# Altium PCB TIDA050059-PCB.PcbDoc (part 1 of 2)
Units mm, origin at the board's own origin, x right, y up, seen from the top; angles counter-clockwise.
Board outline 100 x 120.38 mm, 2 copper layers (Top Layer, Bottom Layer), stack 1.575 mm thick; 126 components, 42 nets, 240 pads, 89 vias.
Unrouted connection lines stored in the file: 41.
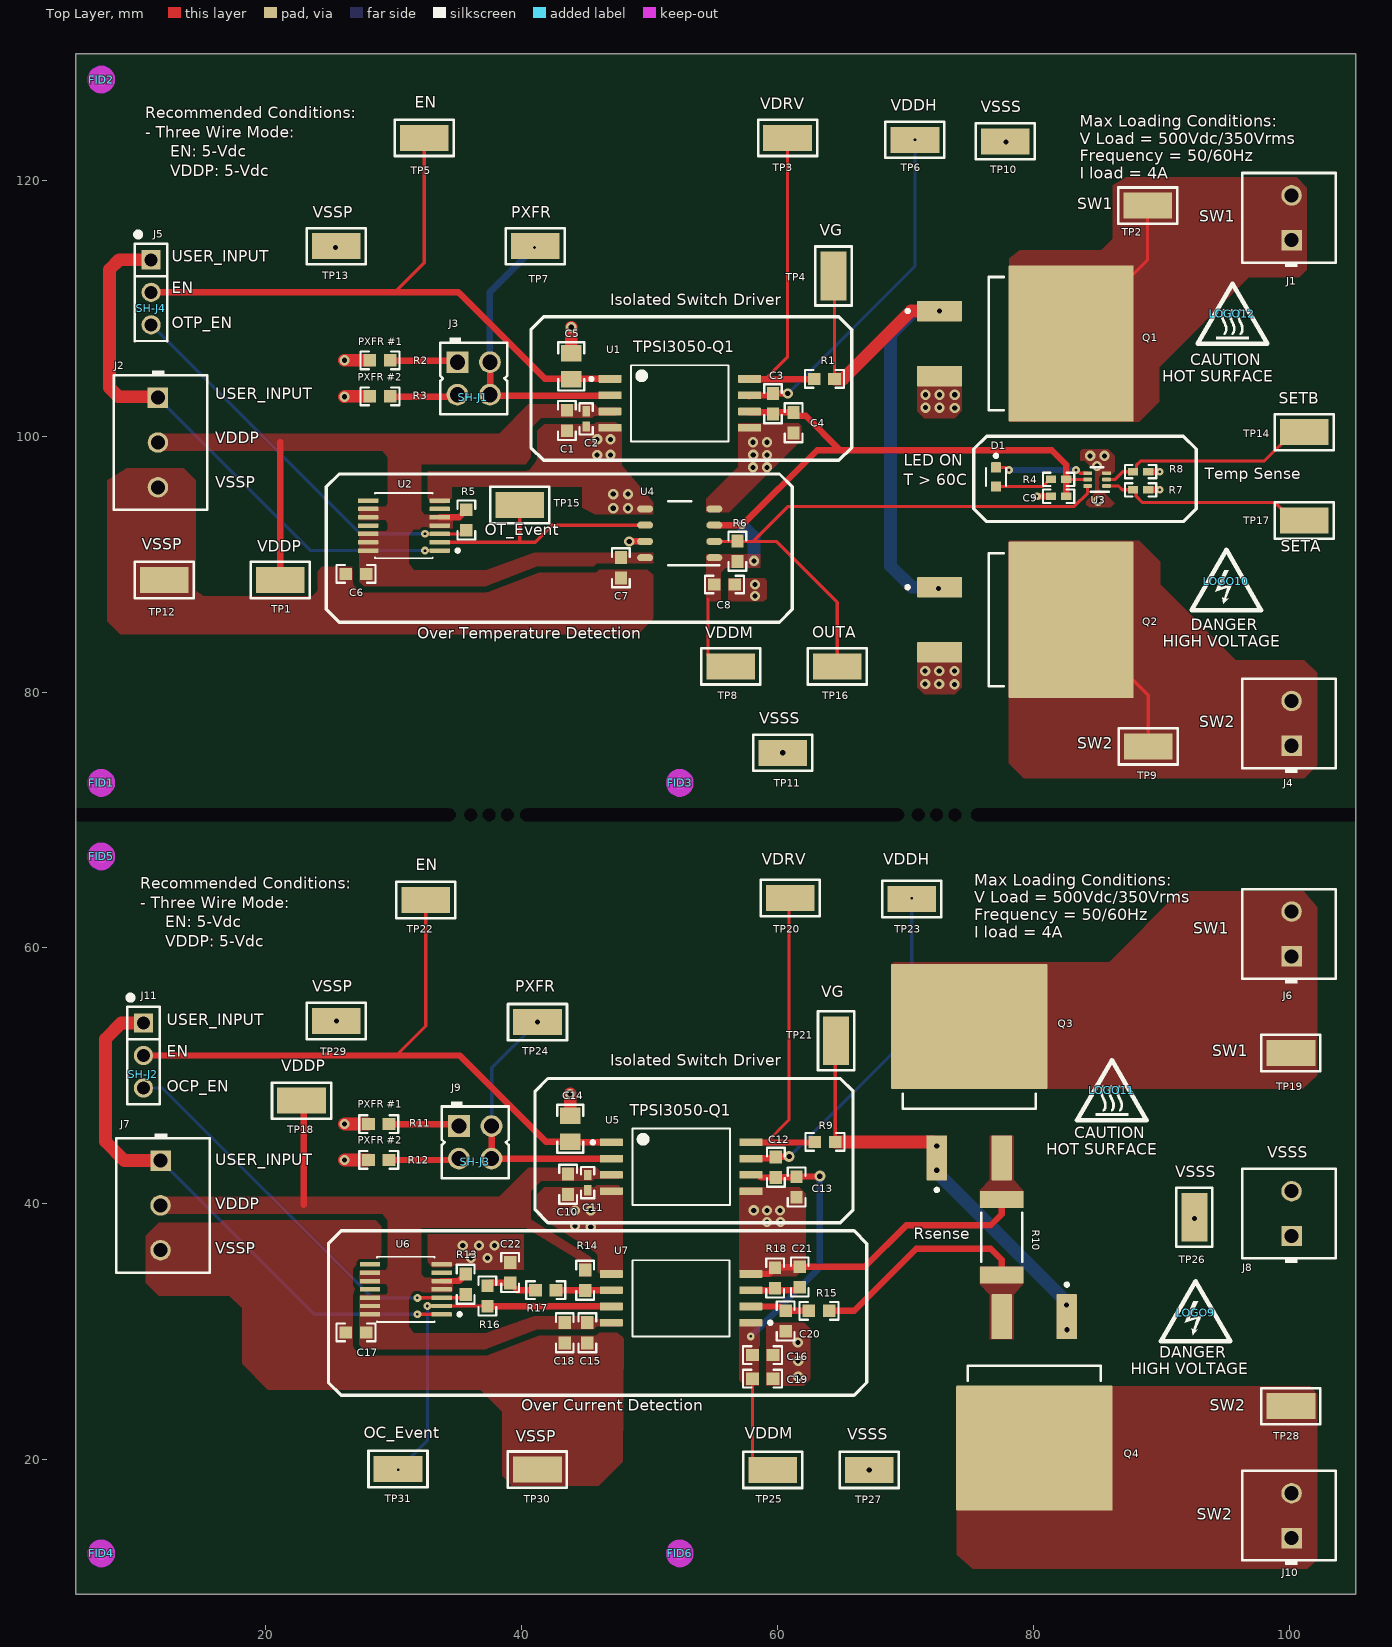
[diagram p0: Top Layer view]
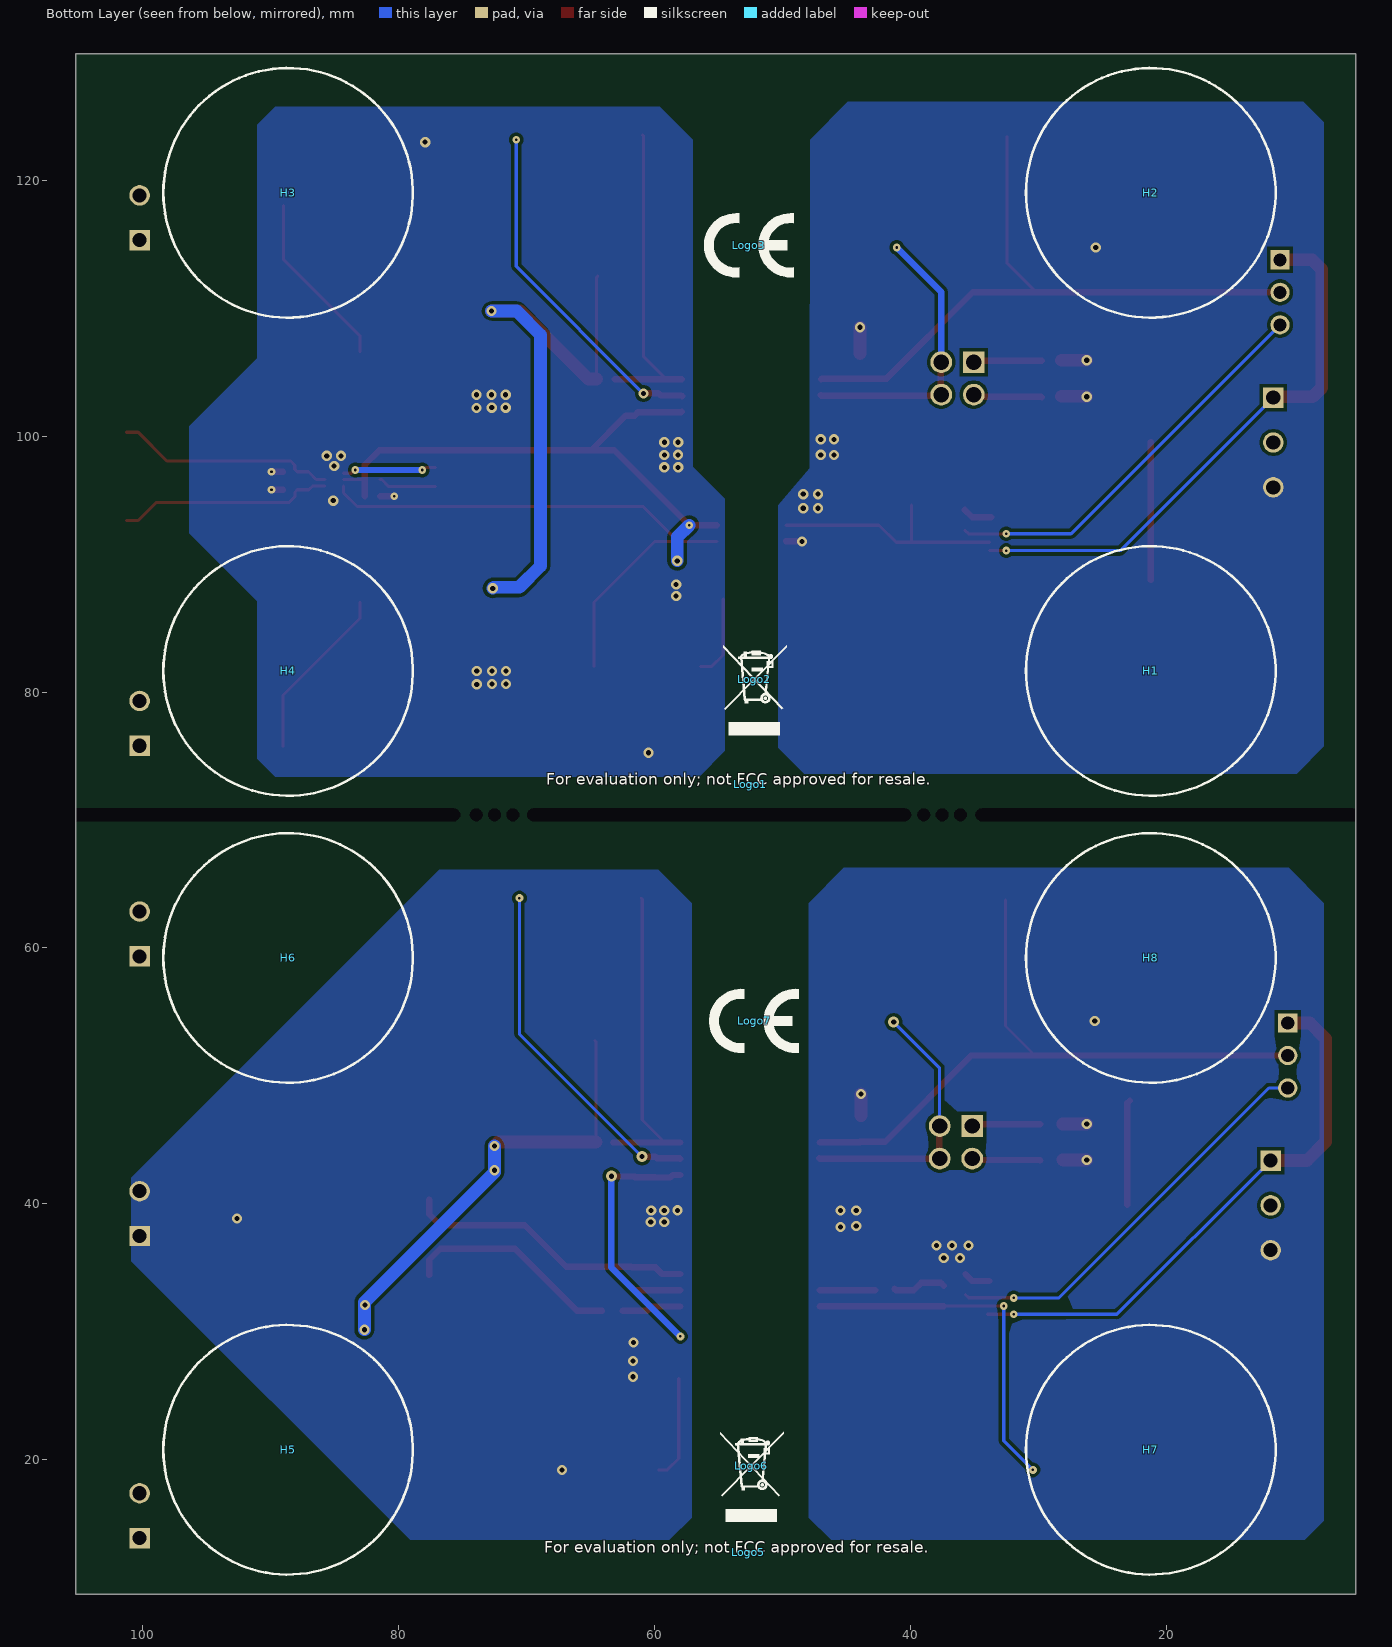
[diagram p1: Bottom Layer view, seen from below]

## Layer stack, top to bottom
Top Solder: solder mask 0.0102, Solder Resist, Dk 3.5
Top Layer: signal copper 0.0356
Dielectric1: core 1.5037, FR-4 High Tg, Dk 4.8
Bottom Layer: signal copper 0.0356
Bottom Solder: solder mask 0.0102, Solder Resist, Dk 3.5

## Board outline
5.2,9.5 105.2,9.5 105.2,129.875 5.2,129.875

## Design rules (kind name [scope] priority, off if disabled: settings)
AcuteAngle [All] p1: minimum=4.50000000000000E+0001 checktracksonly=FALSE
AssemblyTestPointUsage [All] p1: valid=2
BoardOutlineClearance BoardOutlineClearance_MountingHoles [OnCopper and InComponentClass('Mounting Holes')] p1: gap=1 ignorepadtopadclearanceinfootprint=FALSE
BoardOutlineClearance BoardOutlineClearance_Poly [OnCopper and IsPoly] p2: gap=0.635 ignorepadtopadclearanceinfootprint=FALSE
BoardOutlineClearance [OnCopper and Not InComponentClass('Logo') and not InComponentClass('FiducialMark') and not InRegion(1000,500,4000,800) and not InPoly] p3: gap=1.016 ignorepadtopadclearanceinfootprint=FALSE
Clearance Clearance_Keepouts [((IsTrack Or IsArc) And Not InPoly) And IsFree and IsKeepOut vs ((IsTrack Or IsArc) And Not InPoly) And IsFree and IsKeepOut] p1: gap=0 ignorepadtopadclearanceinfootprint=FALSE
Clearance Clearance_Poly [InPolygon] p2: gap=0.254 ignorepadtopadclearanceinfootprint=TRUE except(0.5: Fill-Fill Fill-Poly Fill-Region Poly-Poly Poly-Region Region-Region)
Clearance Clearance_FiducialMark [IsKeepOut and InComponentClass('FiducialMark') vs IsPad and InComponentClass('FiducialMark')] p3: gap=0 ignorepadtopadclearanceinfootprint=FALSE
Clearance [All] p4: gap=0.2 ignorepadtopadclearanceinfootprint=TRUE
ComponentClearance ComponentClearance_MountingHoles_FiducialMarks [InComponentClass('Mounting Holes') vs InComponentClass('FiducialMark')] p1: gap=1.27 collisioncheckmode=3 verticalgap=0.254 showdistances=FALSE
ComponentClearance ComponentClearance_Shunt [InComponentClass('Header') vs InComponentClass('Shunt')] p2: gap=0 collisioncheckmode=3 verticalgap=0 showdistances=FALSE
ComponentClearance ComponentClearance_Logo [InComponentClass('Logo')] p3: gap=0.762 collisioncheckmode=3 verticalgap=0.254 showdistances=FALSE
ComponentClearance ComponentClearance_ScrewToNut [(HasFootprint('NY PMS 440 0025 PH')) vs (HasFootprint('Keystone_1902C'))] p4: gap=0.127 collisioncheckmode=3 verticalgap=0.254 showdistances=FALSE
ComponentClearance ComponentClearance_MountingHoles [InComponentClass('Mounting Holes')] p5: gap=2.54 collisioncheckmode=3 verticalgap=2540 showdistances=FALSE
ComponentClearance ComponentClearance_SmallPassives [HasFootprint('0201*') or HasFootprint('0402*') or HasFootprint('0508') or HasFootprint('0603*') or HasFootprint('0612') or HasFootprint('0805*') or HasFootprint('0815*') or HasFootprint('0830*') or HasFootprint('1206*') or HasFootprint('1210*') or HasFootprint('1808*') or HasFootprint('1812*') or HasFootprint('1825*') or HasFootprint('2010*') or HasFootprint('2220*') or HasFootprint('2225*') or HasFootprint('2512*') or HasFootprint('2728*') or HasFootprint('3518*') vs HasFootprint('0201*') or HasFootprint('0402*') or HasFootprint('0508') or HasFootprint('0603*') or HasFootprint('0612') or HasFootprint('0805*') or HasFootprint('0815*') or HasFootprint('0830*') or HasFootprint('1206*') or HasFootprint('1210*') or HasFootprint('1808*') or HasFootprint('1812*') or HasFootprint('1825*') or HasFootprint('2010*') or HasFootprint('2220*') or HasFootprint('2225*') or HasFootprint('2512*') or HasFootprint('2728*') or HasFootprint('3518*')] p6: gap=0.38 collisioncheckmode=3 verticalgap=0.254 showdistances=FALSE
ComponentClearance ComponentClearance_THtoSMT [IsThruComponent vs IsSMTComponent] p7: gap=0.762 collisioncheckmode=3 verticalgap=0.762 showdistances=FALSE
ComponentClearance ComponentClearance_THtoTH [IsThruComponent vs IsThruComponent] p8: gap=0.508 collisioncheckmode=3 verticalgap=0.762 showdistances=FALSE
ComponentClearance [All] p9: gap=0.508 collisioncheckmode=3 verticalgap=0.254 showdistances=FALSE
DiffPairsRouting [All] p1: maxlimit=2.54 minlimit=0.254 mostfreqgap=0.254 toplayer_minwidth=0.381 toplayer_maxwidth=0.381 toplayer_prefwidth=0.381 bottomlayer_minwidth=0.381 bottomlayer_maxwidth=0.381 bottomlayer_prefwidth=0.381 maxuncoupledlength=25.4
FabricationTestPointUsage TestPointUsage [All] p1: valid=2 allowmultiple=FALSE
FabricationTestpoint Testpoint [All] p1: side=3 testpointundercomponent=TRUE minsize=1.016 maxsize=2.54 preferedsize=1.524 minholesize=0 maxholesize=1.016 preferedholesize=0.813 testpointgrid=0.025 allowsidetop=TRUE allowsidebottom=TRUE usegrid=TRUE gridtolerance=0
FanoutControl Fanout_LCC [IsLCC] p1: bgadir=Out bgaviamode=Centered fanoutstyle=Auto fanoutdirection=Alternating viagrid=0.025 // Fanout_LCC (Default Rule)
FanoutControl Fanout_BGA [IsBGA] p2: bgadir=Out bgaviamode=Centered fanoutstyle=Auto fanoutdirection=Alternating viagrid=0.025 // Fanout_BGA (Default Rule)
FanoutControl Fanout_Default [All] p4: bgadir=Out bgaviamode=Centered fanoutstyle=Auto fanoutdirection=Alternating viagrid=0.025 // Fanout_Default (Default Rule)
FanoutControl Fanout_Small [(CompPinCount < 5)] p5: bgadir=Out bgaviamode=Centered fanoutstyle=Auto fanoutdirection=OutThenIn viagrid=0.025 // Fanout_Small (Default Rule)
HoleSize [All] p1: absolutevalues=TRUE maxlimit=6.375 minlimit=0.2 maxpercent=80.000 minpercent=20.000
MinimumAnnularRing MinimumAnnularRing_ThermalPadVias [IsVia and InAnyComponent] p1: minimumring=0.15
MinimumAnnularRing [All] p2: minimumring=0.2
MinimumSolderMaskSliver MinimumSolderMaskSliver_Logo [InComponentClass('Logo') vs InComponentClass('Logo')] p1: minsoldermaskwidth=0.018
MinimumSolderMaskSliver [All] p2: minsoldermaskwidth=0.1
PlaneClearance [All] p1: clearance=0.5
PlaneConnect [All] p1: planeconnectstyle=Direct reliefexpansion=0.254 reliefentries=4 reliefconductorwidth=0.254 reliefairgap=0.254
PolygonConnect [All] p1: connectstyle=Direct reliefconductorwidth=0.254 reliefentries=4 polygonreliefangle="90 Angle" airgapwidth=0.254
RoutingVias ThermalPadVias [IsVia and InAnyComponent] p1: holewidth=0.4 width=0.8 viastyle="Through Hole" minholewidth=0.2 minwidth=0.5 maxholewidth=1 maxwidth=1.6
RoutingVias [All] p2: holewidth=0.406 width=0.864 viastyle="Through Hole" minholewidth=0.2 minwidth=0.61 maxholewidth=1.016 maxwidth=1.651
SilkToBoardRegionClearance [Not ((IsComment or IsDesignator) And (Hide <> 'False')) and not InRegion(1000,500,4000,800)] p1:
SilkToSilkClearance SilkToSilkClearance_Pb-FreeLogo [(HasFootprint('Pb-Free_Overlay_Medium') OR HasFootprint('Pb-Free_Overlay_Small')) vs (HasFootprint('Pb-Free_Overlay_Medium') OR HasFootprint('Pb-Free_Overlay_Small'))] p1: silktosilkclearance=0
SilkToSilkClearance [All] p2: silktosilkclearance=0.1
SilkToSolderMaskClearance SilkToComponentPadClearance [(IsPad or IsFill or IsRegion) and InAnycomponent] p1: minsilkscreentomaskgap=0.127 clearancetoexposedcopper=TRUE
SilkToSolderMaskClearance "Silk to Solder Mask Opening" [All] p2: minsilkscreentomaskgap=0.1 clearancetoexposedcopper=FALSE
SolderMaskExpansion [All] p1: expansion=0.05 istentingtop=FALSE
UnRoutedNet [All] p1: checkbadconnections=TRUE
Width [All] p1: maxlimit=1 minlimit=0.25 preferedwidth=0.5 minimp=50.000000 maximp=50.000000 favimp=50.000000 checkconnectedcopper=TRUE
13 further rules are at their usual default settings.

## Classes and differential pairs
component class TIDA050059-Schematic_2: C10 C11 C12 C13 C14 C15 C16 C17 C18 C19 C20 C21 C22 J6 J7 J8 J9 J10 J11 Q3 Q4 R9 R10 R11 R12 R13 R14 R15 R16 R17 R18 SH-J3 SH-J4 TP18 TP19 TP20 TP21 TP22 TP23 TP24 TP25 TP26 TP27 TP28 TP29 TP30 TP31 U5 U6 U7
component class TIDA050059-Schematic_1: C1 C2 C3 C4 C5 C6 C7 C8 C9 D1 J1 J2 J3 J4 J5 Q1 Q2 R1 R2 R3 R4 R5 R6 R7 R8 SH-J1 SH-J2 TP1 TP2 TP3 TP4 TP5 TP6 TP7 TP8 TP9 TP10 TP11 TP12 TP13 TP14 TP15 TP16 TP17 U1 U2 U3 U4
component class Shunt: SH-J1 SH-J2 SH-J3 SH-J4
component class Header: J3 J5 J9 J11
component class TIDA050059-Hardware: FID1 FID2 FID3 FID4 FID5 FID6 H1 H2 H3 H4 H5 H6 H7 H8 Logo1 Logo2 Logo3 Logo5 Logo6 Logo7 LOGO9 LOGO10 LOGO11 LOGO12 ZZ1 ZZ2 ZZ3 ZZ4
component class FiducialMark: FID1 FID2 FID3 FID4 FID5 FID6
component class AssemblyNote: ZZ1 ZZ2 ZZ3 ZZ4

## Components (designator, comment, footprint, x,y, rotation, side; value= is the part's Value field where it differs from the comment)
C1 "GRM188R71E224KA88D" 0603 43.586,101.213 r270 top value=0.22uF
C2 "GRM155R71E104KE14D" 0402 45.089,101.338 r270 top value=0.1uF
C3 "UMK107AB7105KA-T" 0603 59.681,102.513 r270 top value=1uF
C4 "UMK107AB7105KA-T" 0603 61.298,101.038 r270 top value=1uF
C5 "C0805C104K1RACTU" 0805_HV 43.922,105.44 r90 top value=0.1uF
C6 "GCM188R71E104KA57D" 0603 27.11,89.225 r180 top value=0.1uF
C7 "GCM188R71E104KA57D" 0603 47.797,89.7 r270 top value=0.1uF
C8 "GCM188R71E104KA57D" 0603 55.9,88.4 r180 top value=0.1uF
C9 "GRM155R71E104KE14D" 0402 82,95.295 r0 top value=0.1uF
C10 "GRM188R71E224KA88D" 0603 43.675,41.55 r270 top value=0.22uF
C11 "GRM155R71E104KE14D" 0402 45.2,41.675 r270 top value=0.1uF
C12 "UMK107AB7105KA-T" 0603 59.9,42.87 r270 top value=1uF
C13 "UMK107AB7105KA-T" 0603 61.525,41.33 r270 top value=1uF
C14 "C0805C104K1RACTU" 0805_HV 43.85,45.875 r90 top value=0.1uF
C15 "GCM188R71E104KA57D" 0603 45.177,29.95 r270 top value=0.1uF
C16 "GCM188R71E104KA57D" 0603 58.873,28.2 r180 top value=0.1uF
C17 "GCM188R71E104KA57D" 0603 27.1,29.971 r180 top value=0.1uF
C18 "GCM188R71E105KA64D" 0603 43.413,29.935 r270 top value=1uF
C19 "GCM188R71E105KA64D" 0603 58.873,26.35 r180 top value=1uF
C20 "C1608X7R1H103K080AA" 0603 60.675,30.855 r270 top value=0.01uF
C21 "C0603C102J5RACTU" 0603 61.775,34.3 r90 top value=1000pF
C22 "CGA3E3X7R1H224K080AB" 0603 39.157,34.639 r90 top value=0.22uF
D1 "LSL29K-G1H2-1-Z" FP-LSL29K-G1H2-1-Z_0603-0 77.1,96.8 r270 top
FID1 "Fiducial" Fiducial10-20 7.2,72.9 r0 top
FID2 "Fiducial" Fiducial10-20 7.2,127.85 r0 top
FID3 "Fiducial" Fiducial10-20 52.4,72.9 r0 top
FID4 "Fiducial" Fiducial10-20 7.2,12.7 r0 top
FID5 "Fiducial" Fiducial10-20 7.2,67.158 r0 top
FID6 "Fiducial" Fiducial10-20 52.4,12.7 r0 top
H1 "SJ-5017 (BLACK)" 3M_SJ-5017BLACK 21.2,81.644 r180 bottom
H2 "SJ-5017 (BLACK)" 3M_SJ-5017BLACK 21.2,119 r180 bottom
H3 "SJ-5017 (BLACK)" 3M_SJ-5017BLACK 88.6,119 r180 bottom
H4 "SJ-5017 (BLACK)" 3M_SJ-5017BLACK 88.6,81.644 r180 bottom
H5 "SJ-5017 (BLACK)" 3M_SJ-5017BLACK 88.6,20.8 r180 bottom
H6 "SJ-5017 (BLACK)" 3M_SJ-5017BLACK 88.6,59.225 r180 bottom
H7 "SJ-5017 (BLACK)" 3M_SJ-5017BLACK 21.2,20.8 r180 bottom
H8 "SJ-5017 (BLACK)" 3M_SJ-5017BLACK 21.2,59.225 r180 bottom
J1 "0393570002" MOLEX_39357-0002 100.2,117.05 r90 top
J2 "0393570003" MOLEX_39357-0003 11.63,99.492 r270 top
J3 "PBC02DAAN" Sullins_PxC02DAAN 36.3,104.5 r0 top
J4 "0393570002" MOLEX_39357-0002 100.2,77.55 r90 top
J5 "PEC03SAAN" CONN_PEC03SAAN 11.1,111.225 r270 top
J6 "0393570002" MOLEX_39357-0002 100.2,61.1 r90 top
J7 "0393570003" MOLEX_39357-0003 11.836,39.893 r270 top
J8 "0393570002" MOLEX_39357-0002 100.2,39.25 r90 top
J9 "PBC02DAAN" Sullins_PxC02DAAN 36.42,44.82 r0 top
J10 "0393570002" MOLEX_39357-0002 100.2,15.65 r90 top
J11 "PEC03SAAN" CONN_PEC03SAAN 10.5,51.6 r270 top
Logo1 "FCC disclaimer" FCC_disclaimer 52.495,72.8 r180 bottom
Logo2 "WEEE logo" WEEE_Minimum 52.172,81 r180 bottom
Logo3 "CE Mark" CE_Mark_5mm 52.6,114.9 r180 bottom
Logo5 "FCC disclaimer" FCC_disclaimer 52.644,12.8 r180 bottom
Logo6 "WEEE logo" WEEE_Minimum 52.418,19.542 r180 bottom
Logo7 "CE Mark" CE_Mark_5mm 52.2,54.3 r180 bottom
LOGO9 "DANGER HIGH VOLTAGE" IEC_HighVoltage_Small 92.7,31.5 r0 top
LOGO10 "DANGER HIGH VOLTAGE" IEC_HighVoltage_Small 95.1,88.638 r0 top
LOGO11 "CAUTION HOT SURFACE" IEC_HotSurface_Small 86.151,48.9 r0 top
LOGO12 "CAUTION HOT SURFACE" IEC_HotSurface_Small 95.583,109.566 r0 top
Q1 "STB43N65M5" FP-STB43N65M5_D2PAK-MFG 81.202,107.223 r270 top
Q2 "STB43N65M5" FP-STB43N65M5_D2PAK-MFG 81.202,85.64 r270 top
Q3 "STB43N65M5" FP-STB43N65M5_D2PAK-MFG 75.02,52.102 r0 top
Q4 "STB43N65M5" FP-STB43N65M5_D2PAK-MFG 80.1,22.7 r180 top
R1 "ERJ-3GEY0R00V" 0603 63.7,104.461 r0 top value=0
R2 "CRCW06037K32FKEA" 0603 28.976,105.915 r0 top value=7.32k
R3 "CRCW060320K0FKEA" 0603 28.976,103.104 r0 top value=20.0k
R4 "CRCW04022K70JNED" 0402 82,96.61 r0 top value=2.7k
R5 "CRCW060310K0JNEA" 0603 35.721,93.435 r90 top value=10k
R6 "CRCW060310K0JNEA" 0603 56.9,91 r270 top value=10k
R7 "CRCW040278K7FKED" 0402 88.4,95.799 r180 top value=78.7k
R8 "CRCW040238K3FKED" 0402 88.4,97.215 r180 top value=38.3k
R9 "ERJ-3GEY0R00V" 0603 63.75,44.85 r0 top value=0
R10 "NA" 2512 77.56,37.4 r90 top value=0.01
R11 "CRCW06037K32FKEA" 0603 28.875,46.245 r0 top value=7.32k
R12 "CRCW060320K0FKEA" 0603 28.875,43.45 r0 top value=20.0k
R13 "CRCW060310K0JNEA" 0603 35.675,33.725 r90 top value=10k
R14 "CRCW0603560KFKEA" 0603 45.011,34.043 r90 top value=560k
R15 "RMCP0603JT100R" 0603 63.275,31.655 r0 top value=100
R16 "CRCW06031K00JNEA" 0603 37.37,32.81 r90 top value=1.0k
R17 "CRCW0603560KFKEA" 0603 41.925,33.263 r0 top value=560k
R18 "RC0603FR-071K2L" 0603 59.85,34.225 r270 top value=1.20k
SH-J1 "SNT-100-BK-G" SNT-100-BK-G 36.283,103.021 r180 top value=1x2
SH-J2 "SNT-100-BK-G" SNT-100-BK-G 10.5,50.125 r90 top value=1x2
SH-J3 "SNT-100-BK-G" SNT-100-BK-G 36.42,43.295 r180 top value=1x2
SH-J4 "SNT-100-BK-G" SNT-100-BK-G 11.1,110 r90 top value=1x2
TP1 "5019" Keystone_5019 21.2,88.75 r180 top
TP2 "5019" Keystone_5019 88.95,118 r180 top
TP3 "5019" Keystone_5019 60.822,123.291 r180 top
TP4 "5019" Keystone_5019 64.413,112.5 r90 top
TP5 "5019" Keystone_5019 32.441,123.291 r0 top
TP6 "5019" Keystone_5019 70.775,123.142 r180 top
TP7 "5019" Keystone_5019 41.114,114.83 r180 top
TP8 "5019" Keystone_5019 56.375,82 r0 top
TP9 "5019" Keystone_5019 89,75.75 r180 top
TP10 "5019" Keystone_5019 77.825,123.027 r0 top
TP11 "5019" Keystone_5019 60.45,75.25 r0 top
TP12 "5019" Keystone_5019 12.138,88.751 r180 top
TP13 "5019" Keystone_5019 25.576,114.83 r180 top
TP14 "5019" Keystone_5019 101.2,100.3 r0 top
TP15 "5019" Keystone_5019 39.896,94.607 r0 top
TP16 "5019" Keystone_5019 64.7,82 r0 top
TP17 "5019" Keystone_5019 101.2,93.4 r180 top
TP18 "5019" Keystone_5019 22.85,48.067 r0 top
TP19 "5019" Keystone_5019 100.15,51.8 r0 top
TP20 "5019" Keystone_5019 61.025,63.9 r180 top
TP21 "5019" Keystone_5019 64.614,52.759 r270 top
TP22 "5019" Keystone_5019 32.55,63.75 r180 top
TP23 "5019" Keystone_5019 70.525,63.825 r180 top
TP24 "5019" Keystone_5019 41.286,54.211 r180 top
TP25 "5019" Keystone_5019 59.673,19.228 r180 top
TP26 "5019" Keystone_5019 92.6,38.976 r90 top
TP27 "5019" Keystone_5019 67.2,19.228 r0 top
TP28 "5019" Keystone_5019 100.15,24.2 r180 top
TP29 "5019" Keystone_5019 25.576,54.302 r0 top
TP30 "5019" Keystone_5019 41.281,19.25 r0 top
TP31 "5019" Keystone_5019 30.385,19.3 r180 top
U1 "TPSI3050QDWZRQ1" DWZ0008A-MFG 52.4,102.552 r0 top
U2 "SN74HCS09PWR" PW0014A-MFG 30.85,93 r180 top
U3 "TMP392A2DRLR" DRL0006A 85,96.595 r180 top
U4 "ISO7310FCDR" D0008B_L 52.398,92.4 r180 top
U5 "TPSI3050QDWZRQ1" DWZ0008A-MFG 52.509,42.909 r0 top
U6 "SN74HCS09PWR" PW0014A-MFG 31,33.33 r180 top
U7 "AMC23C14QDWVRQ1" DWV0008A-MFG 52.5,32.628 r180 top
ZZ1 "This Assembly Note is for PCB labels only" AssemblyNoteLabel 135.399,86.025 r0 top
ZZ2 "These assemblies are ESD sensitive, ESD precautions shall be observed." AssemblyNote 135.399,83.259 r0 top
ZZ3 "These assemblies must be clean and free from flux and all contaminants. Use of no clean flux is not acceptable." AssemblyNote 135.399,81.01 r0 top
ZZ4 "These assemblies must comply with workmanship standards IPC-A-610 Class 2, unless otherwise specified." AssemblyNote 135.399,78.761 r0 top

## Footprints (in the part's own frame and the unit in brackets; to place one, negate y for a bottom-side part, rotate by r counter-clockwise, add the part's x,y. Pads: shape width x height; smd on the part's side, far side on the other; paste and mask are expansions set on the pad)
3M_SJ-5017BLACK [mm] "Bumpon, Cylindrical, 0.75 X 0.38 inch, Black"
  silkscreen extent -9.75,-9.75 9.75,9.75, body extent -9.75,-9.75 9.75,9.75, height 10.1
0402 [mm] "0402 from SM-752 data"
  rect 0.8x0.6 smd: 1(-0.6,0) 2(0.6,0)
  silkscreen extent -1.22,-0.52 1.22,0.52, body extent -0.55,-0.3 0.55,0.3, height 0.6
0603 [mm] "0603 from SM-752 data"
  rect 1x0.95 smd: 1(-0.8,0) 2(0.8,0)
  silkscreen extent -1.52,-0.69 1.52,0.69, body extent -0.87,-0.47 0.87,0.47, height 1
0805_HV [mil] "0805 with 30mil clearance between pads"
  rect 50x63 smd: 1(-40,0) 2(40,0)
  silkscreen extent -74,-40 74,40, body extent -43,-29 43,29, height 57
2512 [mm] "Chip Resistor, Body 6.3x3.2mm, IPC Medium Density"
  rect 1.3x3.4 smd: 1(-2.95,0) 2(2.95,0)
  silkscreen extent -1.9,-1.6 1.9,1.6, body extent -3.22,-1.67 3.22,1.67, height 0.71
AssemblyNote [mm] "Assembly Note"
AssemblyNoteLabel [mm] "Assembly Note for PCB Labels"
CE_Mark_5mm [mm] "Minimum text height for CE Mark"
  silkscreen extent -3.5,-2.5 3.5,2.5
CONN_PEC03SAAN [mm] "SULLINS"
  rect 1.5x1.5 hole 1.016: 1(-2.54,0)
  round 1.5 hole 1.016: 2(0,0) 3(2.54,0)
  silkscreen extent -4.72,-1.27 3.81,1.27, body extent -3.84,-1.3 3.84,1.3, height 8.38
D0008B_L [mm] "SOIC, 8-Leads, Body 4.9x3.9mm, Pitch 1.27mm, IPC High Density"
  oval 1.25x0.55 smd: 1(-2.7,1.905) 2(-2.7,0.635) 3(-2.7,-0.635) 4(-2.7,-1.905) 5(2.7,-1.905) 6(2.7,-0.635) 7(2.7,0.635) 8(2.7,1.905)
  silkscreen extent -3.1,-2.5 0.9,2.5, body extent -3,-2.45 3,2.45, height 1.63
DRL0006A [mm] "SOTFL, 6-Flat Leads, Body 1.2x1.6x0.6mm, Pitch 0.5mm, TI recommended"
  rrect33% 0.67x0.3 smd: 1(-0.74,0.5) 2(-0.74,0) 3(-0.74,-0.5) 4(0.74,-0.5) 5(0.74,0) 6(0.74,0.5)
  silkscreen extent -0.9,-0.95 0.5,0.95, body extent -0.8,-0.8 0.8,0.8, height 0.61
DWV0008A-MFG [mm]
  rrect17% 1.8x0.6 smd paste+0 mask+0: 1(-5.45,1.905) 2(-5.45,0.635) 3(-5.45,-0.635) 4(-5.45,-1.905) 5(5.45,-1.905) 6(5.45,-0.635) 7(5.45,0.635) 8(5.45,1.905)
  silkscreen extent -7.1,-2.98 3.8,2.98, body extent -6.45,-3.22 6.45,3.22, height 0.25
DWZ0008A-MFG [mm]
  rrect17% 1.8x0.6 smd paste+0 mask+0: 1(-5.45,1.905) 2(-5.45,0.635) 3(-5.45,-0.635) 4(-5.45,-1.905) 5(5.45,-1.905) 6(5.45,-0.635) 7(5.45,0.635) 8(5.45,1.905)
  silkscreen extent -7.02,-2.98 3.8,2.98, body extent -6.45,-3.22 6.45,3.22, height 0.25
FCC_disclaimer [mm]
Fiducial10-20 [mm]
  round 1 smd mask+0.5: 1(0,0)
  Top Layer keep-out circle w1.178: c0,0 r0.5
FP-LSL29K-G1H2-1-Z_0603-0 [mm]
  rrect13% 0.8x0.8 smd paste-1000 mask+0: 1(-0.75,0) 2(0.75,0)
  silkscreen extent -1.77,-0.77 0.7,0.77, body extent -1.25,-0.55 1.25,0.55, height 0.25
FP-STB43N65M5_D2PAK-MFG [mm]
  rrect6% 1.6x3.5 smd paste+0 mask+0: 1(-2.54,-8.503) 3(2.54,-8.503)
  rrect1% 12.2x9.75 smd paste+0 mask+0: 4(0,1.773)
  silkscreen extent -5.2,-11.12 5.2,-3.48, body extent -6.2,-10.35 6.2,6.75, height 0.25
IEC_HighVoltage_Small [mm]
  silkscreen extent -2.72,-2.24 2.72,2.47
IEC_HotSurface_Small [mm]
  silkscreen extent -2.72,-2.36 2.72,2.35
Keystone_5019 [mm] "Test Point, Miniature, SMT"
  rect 3.8x2.03 smd: 1(0,0)
  silkscreen extent -2.31,-1.42 2.31,1.42, body extent -1.9,-1.02 1.9,1.02, height 2.29
MOLEX_39357-0002 [mm] "Terminal Block, 3.5 mm, 2x1, TH"
  rect 1.6x1.6 hole 1.1: 1(-1.75,0)
  round 1.6 hole 1.1: 2(1.75,0)
  silkscreen extent -3.86,-3.45 3.5,3.84, body extent -3.55,-3.45 3.56,3.84, height 8.51
MOLEX_39357-0003 [mm] "Terminal Block, 3.5 mm, 3x1, TH"
  rect 1.6x1.6 hole 1.1: 1(-3.5,0)
  round 1.6 hole 1.1: 2(0,0) 3(3.5,0)
  silkscreen extent -5.61,-3.45 5.25,3.84, body extent -5.25,-3.45 5.16,3.84, height 8.51
PW0014A-MFG [mm]
  rrect29% 1.6x0.35 smd paste-1000 mask+0: 1(-2.8,1.95) 2(-2.8,1.3) 3(-2.8,0.65) 4(-2.8,0) 5(-2.8,-0.65) 6(-2.8,-1.3) 7(-2.8,-1.95) 8(2.8,-1.95) 9(2.8,-1.3) 10(2.8,-0.65) 11(2.8,0) 12(2.8,0.65) 13(2.8,1.3) 14(2.8,1.95)
  silkscreen extent -4.33,-2.55 2.25,2.55, body extent -3.7,-2.8 3.7,2.8, height 0.25
SNT-100-BK-G [mil] "Samtec STEP model"
  round 1 on Mech3: 0(0,0)
  body extent -100,-50 100,50, height 344
Sullins_PxC02DAAN [mm] "Header, 2.54mm, 2x2, TH"
  rect 1.7x1.7 hole 1.2: 1(-1.27,1.27)
  round 1.7 hole 1.2: 2(1.27,1.27) 3(-1.27,-1.27) 4(1.27,-1.27)
  silkscreen extent -2.61,-2.8 2.61,3.2, body extent -2.61,-2.8 2.61,2.8, height 8.58
WEEE_Minimum [mm] "WEEElie bin"
  silkscreen extent -2.42,-4.38 2.52,2.65

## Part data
C1 C10: library part CMP-0007415-4, "CAP, CERM, 0.22 uF, 25 V, +/- 10%, X7R, 0603", Cap_Case=0603, Manufacturer=MuRata, Supplier Part Number 1=490-3290-1-ND, TempCo=X7R, Tolerance_%=10%, Value1=Unknown, Value2=25V, ValueDisplayed=0.22uF
C2 C9 C11: library part CMP-0006659-2, "CAP, CERM, 0.1 uF, 25 V, +/- 10%, X7R, 0402", Cap_Case=0402, Manufacturer=MuRata, Supplier Part Number 1=490-10698-1-ND, TempCo=X7R, Tolerance_%=10%, Value1=Unknown, Value2=25V, ValueDisplayed=0.1uF
C3 C4 C12 C13: library part CMP-0007508-5, "CAP, CERM, 1 uF, 50 V, +/- 10%, X7R, 0603", Cap_Case=0603, Manufacturer="Taiyo Yuden", Supplier Part Number 1=587-3247-1-ND, TempCo=X7R, Tolerance_%=10%, Value1=Unknown, Value2=50V, ValueDisplayed=1uF
C5 C14: library part CMP-0007722-2, "CAP, CERM, 0.1 uF, 100 V, +/- 10%, X7R, 0805", Cap_Case=0805, Manufacturer=Kemet, Supplier Part Number 1=399-3486-1-ND, TempCo=X7R, Tolerance_%=10%, Value1="0.064 ohm", Value2=100V, ValueDisplayed=0.1uF
C6 C7 C8 C15 C16 C17: library part CMP-0084679-1, "CAP, CERM, 0.1 µF, 25 V,+/- 10%, X7R, AEC-Q200 Grade 1, 0603", Cap_Case=0603, Manufacturer=MuRata, TempCo=X7R, Tolerance_%=10%, Value2=25V, ValueDisplayed=0.1µF
C18 C19: library part CMP-0007139-4, "CAP, CERM, 1 uF, 25 V, +/- 10%, X7R, AEC-Q200 Grade 1, 0603", Cap_Case=0603, Manufacturer=MuRata, Supplier Part Number 1=490-10673-1-ND, TempCo=X7R, Tolerance_%=10%, Value1=Unknown, Value2=25V, ValueDisplayed=1uF
C20: library part CMP-0007043-4, "CAP, CERM, 0.01 uF, 50 V, +/- 10%, X7R, 0603", Cap_Case=0603, Manufacturer=TDK, Supplier Part Number 1=445-1311-1-ND, TempCo=X7R, Tolerance_%=10%, Value1="0.0539 ohm", Value2=50V, ValueDisplayed=0.01uF
C21: library part CMP-0006845-4, "CAP, CERM, 1000 pF, 50 V, +/- 5%, X7R, 0603", Cap_Case=0603, Manufacturer=Kemet, Supplier Part Number 1=399-1083-1-ND, TempCo=X7R, Tolerance_%=5%, Value1=Unknown, Value2=50V, ValueDisplayed=1000pF
C22: library part CMP-0007094-5, "CAP, CERM, 0.22 uF, 50 V, +/- 10%, X7R, AEC-Q200 Grade 1, 0603", Cap_Case=0603, Manufacturer=TDK, Supplier Part Number 1=445-6926-1-ND, TempCo=X7R, Tolerance_%=10%, Value1="0.021699 ohm", Value2=50V, ValueDisplayed=0.22uF
D1: library part CMP-0092845-1, "LED Uni-Color Red 643nm 2-Pin Chip 0603(1608Metric) T/R", Color=Red, Digikey Part Number=475-3124-1-ND, Forward Current=2mA, Manufacturer="OSRAM Opto Semiconductors", Mouser Part Number=720-LSL29K-G1H2-1-Z, Operating Temperature Range="-40°C to +100°C"
FID1 FID2 FID3 FID4 FID5 FID6: library part CMP-0077181-1, "Fiducial mark.  There is nothing to buy or mount.", Manufacturer=N/A
H1 H2 H3 H4 H5 H6 H7 H8: library part CMP-0003997-1, "Bumpon, Cylindrical, 0.75 X 0.38 inch, Black", Manufacturer=3M, Supplier Part Number 1=SJ5017-0-ND
J1 J4 J6 J8 J10: library part CMP-0055341-2, "Terminal Block, 3.5 mm, 2x1, Tin, TH", Manufacturer=Molex, Supplier Part Number 1=WM7877-ND
J2 J7: library part CMP-0055340-2, "Terminal Block, 3.5 mm, 3x1, Tin, TH", Manufacturer=Molex, Supplier Part Number 1=WM7878-ND
J3 J9: library part CMP-0054598-1, "Header, 2.54mm, 2x2, Gold, TH", Color=Black, Current_A=3A, Manufacturer="Sullins Connector Solutions", Supplier Part Number 1=S2011E-02-ND, Voltage_V=1.8kV
J5 J11: library part CMP-0002338-1, "Header, 100mil, 3x1, Tin, TH", Color=Black, Current_A=3A, Manufacturer="Sullins Connector Solutions", Supplier Part Number 1=S1012E-03-ND, Voltage_V=1.8kV
Logo1 Logo5: library part CMP-0074847-1, "FCC_disclaimer"
Logo2 Logo6: library part CMP-0074769-1
Logo3 Logo7: library part CMP-0074844-1
LOGO9 LOGO10: library part CMP-0074835-1, "IEC 61010-1 High Voltage Warning"
LOGO11 LOGO12: library part CMP-0074837-1, "IEC 61010-1 Hot Surface Warning"
Q1 Q2 Q3 Q4: library part CMP-0088026-1, "MOSFET N-CH 650V 42A", Manufacturer=STMicroelectronics
R1 R9: library part CMP-0025874-4, "RES, 0, 5%, 0.1 W, AEC-Q200 Grade 0, 0603", Manufacturer=Panasonic, Power_W=100mW, Supplier Part Number 1=P0.0GCT-ND, TempCo="600 ppm/C", Tolerance_%=5%, Value2=0.1W, Value_Code=0000, ValueDisplayed=0
R2 R11: library part CMP-0022600-4, "RES, 7.32 k, 1%, 0.1 W, AEC-Q200 Grade 0, 0603", Manufacturer=Vishay-Dale, Power_W=100mW, Supplier Part Number 1=541-7.32KHCT-ND, TempCo="100 ppm/C", Tolerance_%=1%, Value2=0.1W, Value_Code=7k32, ValueDisplayed=7.32k
R3 R12: library part CMP-0022204-4, "RES, 20.0 k, 1%, 0.1 W, AEC-Q200 Grade 0, 0603", Manufacturer=Vishay-Dale, Power_W=100mW, Supplier Part Number 1=541-20.0KHCT-ND, TempCo="100 ppm/C", Tolerance_%=1%, Value2=0.1W, Value_Code=20k0, ValueDisplayed=20.0k
R4: library part CMP-0026892-5, "RES, 2.7 k, 5%, 0.063 W, AEC-Q200 Grade 0, 0402", Manufacturer=Vishay-Dale, Power_W=63mW, Supplier Part Number 1=541-2.7KJCT-ND, TempCo="200 ppm/C", Tolerance_%=5%, Value2=0.063W, Value_Code=2k70, ValueDisplayed=2.7k
R5 R6 R13: library part CMP-0025701-4, "RES, 10 k, 5%, 0.1 W, AEC-Q200 Grade 0, 0603", Manufacturer=Vishay-Dale, Power_W=100mW, Supplier Part Number 1=541-10KGCT-ND, TempCo="200 ppm/C", Tolerance_%=5%, Value2=0.1W, Value_Code=10k0, ValueDisplayed=10k
R7: library part CMP-0026551-2, "RES, 78.7 k, 1%, 0.063 W, AEC-Q200 Grade 0, 0402", Manufacturer=Vishay-Dale, Power_W=63mW, Supplier Part Number 1=541-78.7KLCT-ND, TempCo="100 ppm/C", Tolerance_%=1%, Value2=0.063W, Value_Code=78k7, ValueDisplayed=78.7k
R8: library part CMP-0026323-2, "RES, 38.3 k, 1%, 0.063 W, AEC-Q200 Grade 0, 0402", Manufacturer=Vishay-Dale, Power_W=63mW, Supplier Part Number 1=541-38.3KLCT-ND, TempCo="100 ppm/C", Tolerance_%=1%, Value2=0.063W, Value_Code=38k3, ValueDisplayed=38.3k
R10: library part CMP-0015413-2, "RES, 0.01, 1%, 1 W, 2512", Manufacturer="CTS Resistor", PartNumber=73M1R010F, Power_W=1W, Supplier Part Number 1=73M1R010FCT-ND, TempCo="100 ppm/C", Tolerance_%=1%, Value2=3W, Value_Code=R010, ValueDisplayed=0.06
R14 R17: library part CMP-0022496-4, "RES, 560 k, 1%, 0.1 W, AEC-Q200 Grade 0, 0603", Manufacturer=Vishay-Dale, Power_W=100mW, Supplier Part Number 1=541-560KHCT-ND, TempCo="100 ppm/C", Tolerance_%=1%, Value2=0.1W, Value_Code=560k
R15: library part CMP-0860543-1, "RES, 100, 5%, 0.25 W, AEC-Q200 Grade 0, 0603", Manufacturer="Stackpole Electronics Inc", Power_W=250mW, TempCo="100 ppm/C", Tolerance_%=5%, Value2=0.25W, Value_Code=100R, ValueDisplayed=100
R16: library part CMP-0025729-4, "RES, 1.0 k, 5%, 0.1 W, AEC-Q200 Grade 0, 0603", Manufacturer=Vishay-Dale, Power_W=100mW, Supplier Part Number 1=541-1.0KGCT-ND, TempCo="200 ppm/C", Tolerance_%=5%, Value2=0.1W, Value_Code=1k00, ValueDisplayed=1.0k
R18: library part CMP-0022874-5, "RES, 1.20 k, 1%, 0.1 W, 0603", Manufacturer=Yageo, Power_W=100mW, Supplier Part Number 1=311-1.20KHRCT-ND, TempCo="100 ppm/C", Tolerance_%=1%, Value2=0.1W, Value_Code=1k20, ValueDisplayed=1.20k
SH-J1 SH-J2 SH-J3 SH-J4: library part CMP-0003623-3, "Shunt, 100mil, Gold plated, Black", Alternate Manufacturer=3M, Alternate PartNumber=969102-0000-DA, Manufacturer=Samtec, Supplier Part Number 1=SAM8858-ND
TP1 TP2 TP3 TP4 TP5 TP6 TP7 TP8 TP9 TP10 TP11 TP12 TP13 TP14 TP15 TP16 TP17 TP18 TP19 TP20 TP21 TP22 TP23 TP24 TP25 TP26 TP27 TP28 TP29 TP30 TP31: library part CMP-0055162-1, "Test Point, Miniature, SMT", Manufacturer=Keystone, Supplier Part Number 1=36-5019TR-ND
U1 U5: library part CMP-0095183-1, "Automotive Reinforced Isolated Switch Driver With Integrated 10-V Gate Supply", Manufacturer="Texas Instruments", Max Supply Voltage=5.5V, Min Supply Voltage=3V, Nominal Supply Current=4-33mA, Operating Temperature Range="-40°C to +150°C", Output Voltage=10V
U2 U6: library part CMP-0092187-1, "AND Gate IC 4 Channel Schmitt Trigger, Open Drain 14-TSSOP", Digikey Part Number=296-SN74HCS09PWRCT-ND, Manufacturer="Texas Instruments", Max Supply Voltage=6V, Min Supply Voltage=2V, Mouser Part Number=595-SN74HCS09PWR, Nominal Supply Current=0.1uA, Operating Temperature Range="-40°C to +125°C"
U3: library part CMP-0860529-1, "Ultra-Small, Dual-Channel, 0.5-μA, Resistor-Programmable Temperature Switch, DRL0006A (SOT-5X3-6)", Alternate Manufacturer="Texas Instruments"
U4: library part CMP-0076045-1, "Robust EMC, Low Power Single-Channel 1/0 Digital Isolator, Fail-safe Low, D0008B (SOIC-8)", Alternate Manufacturer="Texas Instruments", Alternate PartNumber=ISO7310FCD
U7: library part CMP-0092425-3, "Dual, Fast Response, Reinforced Isolated Window Comparator with Adjustable Threshold, SOICW8", Input Bias Current=0.00001uA, Manufacturer="Texas Instruments", Max Supply Voltage=27V, Min Supply Voltage=2.7V, Operating Temperature Range="to +150°C"
ZZ1: library part CMP-0003616-3
ZZ2: library part CMP-0077236-1
ZZ3: library part CMP-0077237-1
ZZ4: library part CMP-0077238-1

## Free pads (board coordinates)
  round 0 hole 1 slot 30 at 0 deg unplated mask+0.025: 0(19.9,70.4) 0(54.929,70.4)
  round 0 hole 1 unplated mask+0.025: 0(36.074,70.4) 0(37.505,70.4) 0(38.935,70.4) 0(71.039,70.4) 0(72.47,70.4) 0(73.9,70.4)
  round 0 hole 1 slot 30.5 at 0 deg unplated mask+0.025: 0(90.4,70.4)

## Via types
v1: diameter 0.8, hole 0.4, Top Layer to Bottom Layer, tented both sides, 70 vias
v2: diameter 0.61, hole 0.203, Top Layer to Bottom Layer, tented both sides, 16 vias
v3: diameter 0.864, hole 0.406, Top Layer to Bottom Layer, tented both sides, 3 vias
